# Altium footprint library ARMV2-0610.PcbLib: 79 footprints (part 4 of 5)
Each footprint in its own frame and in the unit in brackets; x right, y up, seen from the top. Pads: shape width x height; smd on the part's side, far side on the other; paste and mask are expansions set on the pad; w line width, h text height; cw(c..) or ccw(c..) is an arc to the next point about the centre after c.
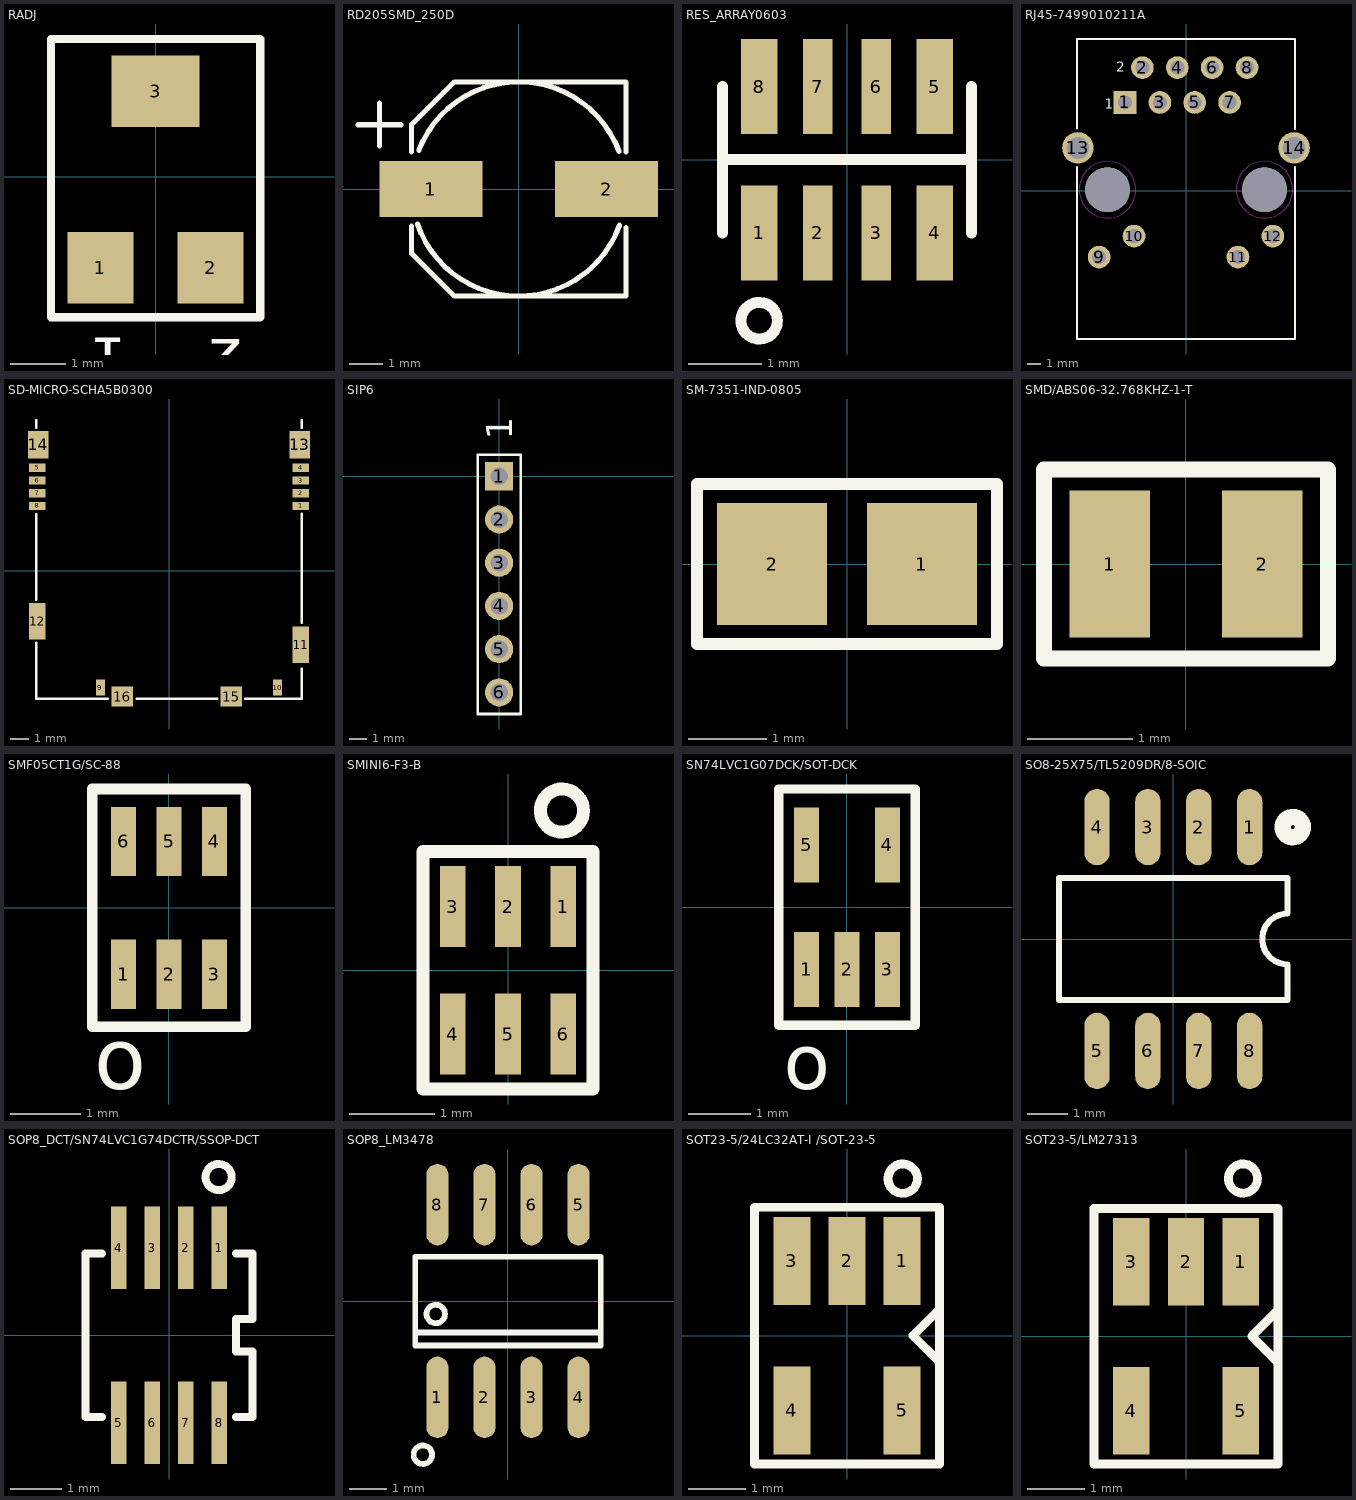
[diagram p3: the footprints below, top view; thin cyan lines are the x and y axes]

## RADJ [mm] "RADJ"
pads (3):
  rect 1.2x1.3 smd: 1(-1,-1.65) 2(1,-1.65)
  rect 1.6x1.3 smd: 3(0,1.55)
Top Overlay:
  lines w0.15: -1.9,-2.55 -1.9,2.5 1.9,2.5 1.9,-2.55 -1.9,-2.55
  text "2" at 1.6,-2.946 h0.79
  text "1" at -0.508,-2.921 h0.79

## RD205SMD_250D [mil] "RD205SMD_250D"
pads (2):
  rect 120x65 smd mask+2: 1(-102.5,0) 2(102.5,0)
Top Overlay:
  lines w6: -187.5,75 -137.5,75 ; -162.5,50 -162.5,100 ; -125,-43 -125,-75 -75,-125 125,-125 125,-45 ; -125,43 -125,75 -75,125 125,125 125,43 ; -118.2,-40.66 ccw(c0,0) 117.61,-42.34 ; -116.52,45.25 cw(c0,0) 117,44

## RES_ARRAY0603 [mm]
pads (8):
  rect 0.5x1.3 smd: 1(-1.2,-1) 4(1.2,-1) 5(1.2,1) 8(-1.2,1)
  rect 0.4x1.3 smd: 2(-0.4,-1) 3(0.4,-1) 6(0.4,1) 7(-0.4,1)
Top Overlay:
  circle w0.15: c-1.2,-2.2 r0.25
  lines w0.15: -1.7,-1 -1.7,1 ; -1.7,0 1.7,0 ; 1.7,-1 1.7,1

## RJ45-7499010211A [mil] "RJ45-7499010211A"
pads (16):
  rect 65x65 hole 40 mask+2: 1(-175,252.5)
  round 65 hole 40 mask+2: 2(-125,352.5) 3(-75,252.5) 4(-25,352.5) 5(25,252.5) 6(75,352.5) 7(125,252.5) 8(175,352.5) 9(-249,-190.5) 10(-149,-130.5) 11(149,-190.5) 12(249,-130.5)
  round 90 hole 63 mask+2: 13(-310,122.5) 14(310,122.5)
  round 128 hole 128 unplated: " "(-225,2.5)
  round 128 hole 128 unplated mask+2: " "(225,2.5)
Top Overlay:
  lines w6: -313,67 -313,-425.5 313,-425.5 313,67 ; -313,178 -313,434.5 313,434.5 313,177
  text "1" at -233,235 h28
  text "2" at -200,340 h28
Keep-Out Layer:
  circle w1: c-225,2.5 r81
  circle w1: c225,2.5 r81

## SD-MICRO-SCHA5B0300 [mil] "SD-MICRO-SCHA5B0300"
pads (16):
  rect 36x18 smd mask+2: 1(285.72,140.22) 2(285.72,167.78) 3(285.72,195.34) 4(285.72,222.9) 5(-285.72,222.9) 6(-285.72,195.34) 7(-285.72,167.78) 8(-285.72,140.22)
  rect 20x35 smd mask+2: 9(-148.62,-253.06) 10(235.24,-253.06)
  rect 35x79 smd mask+2: 11(285.43,-160.38) 12(-285.43,-109.19)
  rect 44x60 smd mask+2: 13(283.32,272.69) 14(-283.32,272.69)
  rect 47x43 smd mask+2: 15(134.84,-272.69) 16(-101.37,-272.69)
Top Overlay:
  lines w6: -287.5,-156.78 -287.5,-277.29 -132.5,-277.29 ; -287.5,-62.28 -287.5,122.27 ; -287.5,309.71 -287.5,325.21 ; -70,-277.29 104.5,-277.29 ; 165.5,-277.29 287.5,-277.29 287.5,-213 ; 287.5,-112.78 287.5,123.22 ; 287.5,309.71 287.5,325.21

## SIP6 [mil] "SIP6"
pads (6):
  rect 65x65 hole 40 mask+2: 1(0,0)
  round 65 hole 40 mask+2: 2(0,-100) 3(0,-200) 4(0,-300) 5(0,-400) 6(0,-500)
Top Overlay:
  lines w6: -50,-550 -50,50 50,50 50,-550 -50,-550
  text "1" at 30.82,84 h60

## SM-7351-IND-0805 [mil] "SM-7351-IND-0805"
pads (2):
  rect 55x61 smd mask+2: 1(37.4,0) 2(-37.4,0)
Top Overlay:
  lines w6: -75,-40 75,-40 75,40 -75,40 -75,-40

## SMD/ABS06-32.768KHZ-1-T [mm]
height 0.6
pads (2):
  rect 0.762x1.4 smd mask+0.051: 1(-0.725,0) 2(0.725,0)
Top Overlay:
  lines w0.152: -1.35,-0.9 -1.35,0.9 1.35,0.9 1.35,-0.9 -1.35,-0.9

## SMF05CT1G/SC-88 [mil]
pads (6):
  rect 14x39 smd: 1(-25.59,-37.4) 2(0,-37.4) 3(25.59,-37.4) 4(25.59,37.4) 5(0,37.4) 6(-25.59,37.4)
Top Overlay:
  lines w6: -43.31,-66.93 -43.31,66.93 43.31,66.93 43.31,-66.93 -43.31,-66.93
  text "o" at -42,-102 h35

## SMINI6-F3-B [mil] "SMINI6-F3-B"
pads (6):
  rect 12x37.4 smd mask+2: 1(25.59,29.53) 2(0,29.53) 3(-25.59,29.53) 4(-25.59,-29.53) 5(0,-29.53) 6(25.59,-29.53)
Top Overlay:
  circle w6: c25,74 r10
  lines w6: -39.37,-55 39.37,-55 39.37,55 -39.37,55 -39.37,-55

## SN74LVC1G07DCK/SOT-DCK [mm]
pads (5):
  rect 0.4x1.2 smd: 1(-0.65,-1) 2(0,-1) 3(0.65,-1) 4(0.65,1) 5(-0.65,1)
Top Overlay:
  lines w0.152: -1.1,-1.9 1.1,-1.9 1.1,1.9 -1.1,1.9 -1.1,-1.9
  text "o" at -1.016,-2.921 h0.89

## SO8-25X75/TL5209DR/8-SOIC [mil]
pads (8):
  oval 25x75 smd mask+2: 1(75,110) 2(25,110) 3(-25,110) 4(-75,110) 5(-75,-110) 6(-25,-110) 7(25,-110) 8(75,-110)
Top Overlay:
  circle w6: c117.5,110 r15
  circle w6: c117.5,110 r10
  circle w6: c117.5,110 r5
  lines w6: -112.5,-60 112.5,-60 112.5,-25 cw(c112.5,0) 112.5,25 112.5,60 -112.5,60 -112.5,-60

## SOP8_DCT/SN74LVC1G74DCTR/SSOP-DCT [mil]
pads (8):
  rect 12x63 smd mask+2: 1(38.4,67) 2(12.8,67) 3(-12.8,67) 4(-38.4,67) 5(-38.4,-67) 6(-12.8,-67) 7(12.8,-67) 8(38.4,-67)
Top Overlay:
  circle w6: c38,121 r10
  lines w6: -51.2,-62.5 -64,-62.5 -64,62.5 -51.2,62.5 ; 51.2,-62.5 64,-62.5 64,-12.5 51.2,-12.5 51.2,12.5 64,12.5 64,62.5 51.2,62.5

## SOP8_LM3478 [mm]
height 1.75
pads (8):
  oval 0.6x2.2 smd: 1(-1.905,-2.6) 2(-0.635,-2.6) 3(0.635,-2.6) 4(1.905,-2.6) 5(1.905,2.6) 6(0.635,2.6) 7(-0.635,2.6) 8(-1.905,2.6)
Top Overlay:
  circle w0.152: c-2.3,-4.15 r0.25
  circle w0.152: c-1.95,-0.35 r0.25
  lines w0.152: -2.5,-0.85 2.5,-0.85 ; -2.5,-1.2 -2.5,1.2 2.5,1.2 2.5,-1.2 -2.5,-1.2

## SOT23-5/24LC32AT-I /SOT-23-5 [mil]
height 57.09
pads (5):
  rect 25x60 smd mask+2: 1(37.5,51) 2(0,51) 3(-37.5,51) 4(-37.5,-51) 5(37.5,-51)
Top Overlay:
  circle w6: c38,107 r10
  lines w6: 62.5,-17.5 45,0 62.5,17.5 ; -62.99,-87.5 62.99,-87.5 62.99,87.5 -62.99,87.5 -62.99,-87.5

## SOT23-5/LM27313 [mil]
height 48.03
pads (5):
  rect 25x60 smd mask+2: 1(37.5,51) 2(0,51) 3(-37.5,51) 4(-37.5,-51) 5(37.5,-51)
Top Overlay:
  circle w6: c39,108 r10
  lines w6: 62.5,-17.5 45,0 62.5,17.5 ; -62.99,-87.5 62.99,-87.5 62.99,87.5 -62.99,87.5 -62.99,-87.5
